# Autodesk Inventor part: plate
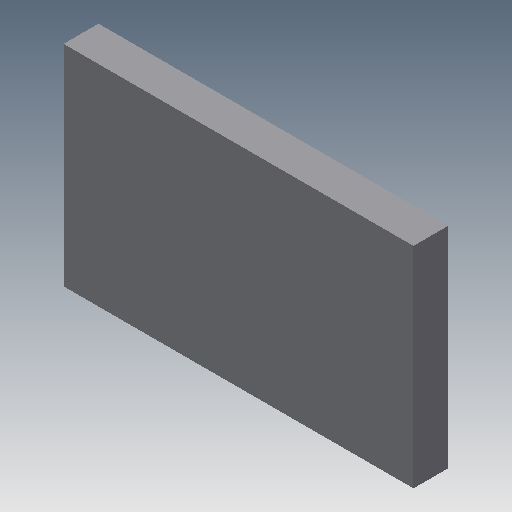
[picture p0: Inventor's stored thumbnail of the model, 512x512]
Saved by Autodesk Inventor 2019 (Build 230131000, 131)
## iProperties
Created: 2010-05
Part Number: plate
Document SubType Name: Modeling
Designer: CADSoft
Density: 1 g/cm^3
Material: Generic
Appearance: Default
Author: CADSoft
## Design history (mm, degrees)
sketch "Sketch1"
  geometry: L1 (101.431, -46.382)-(51.431, -46.382); L2 (51.431, -46.382)-(51.431, -76.382); L3 (51.431, -76.382)-(101.431, -76.382); L4 (101.431, -76.382)-(101.431, -46.382); 1 further point
  constraints: 8 end point, 2 parallel, 1 horizontal, 1 perpendicular
  dimensions: "d0" = 30 distance of L3.end L1.start; "d1" = 50 distance of L1.start L1.end
extrude "Extrusion1" new body sketch "Sketch1" distance "d2" = 5; taper "d3" = 0 deg
body "Solid1"
